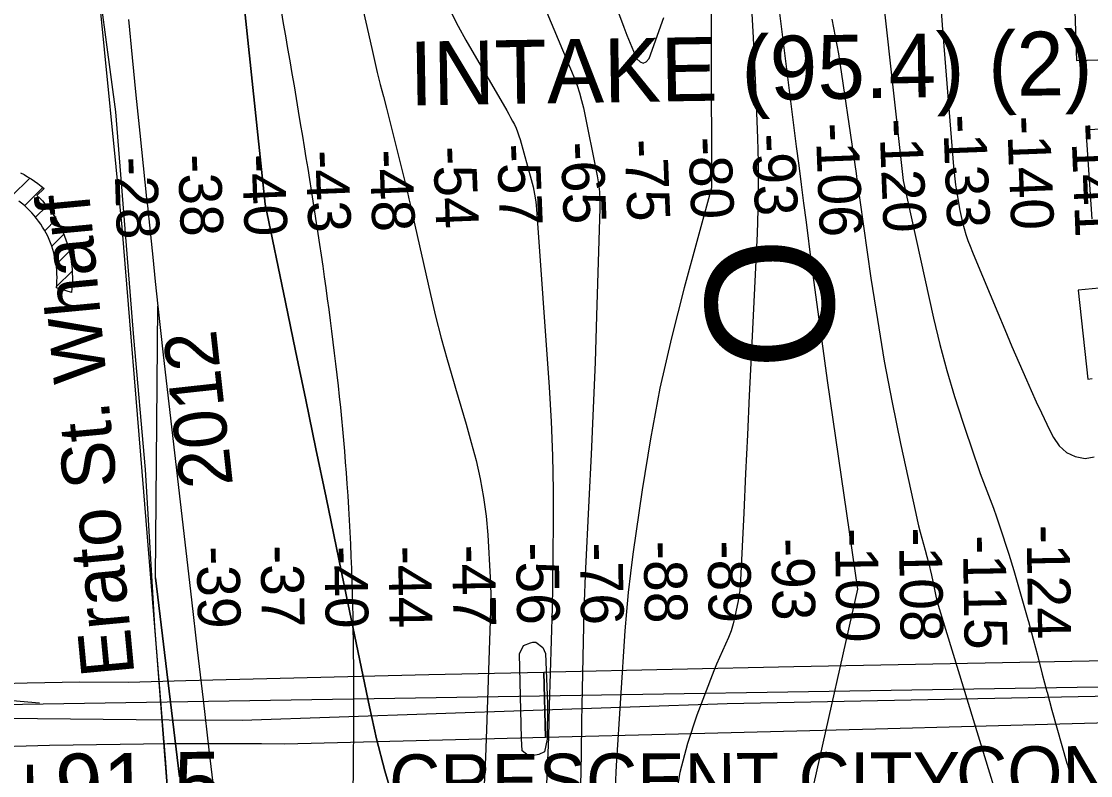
# Model space of a CAD drawing. Extents: x 3677843 to 3715951, y 511991 to 537744.
# Drawn here: x 3683602 to 3685277, y 525377 to 526559 of the extents above; entities that cross this region are included whole.
import ezdxf

# ---------------------------------------------------------------- set-up
doc = ezdxf.new("R2010")
doc.units = 0
for name, color, linetype in [('V-BLDG-IDEN', 7, 'Continuous'), ('V-BLDG-OTLN', 7, 'Continuous'), ('V-BRDG-IDEN', 7, 'Continuous'), ('V-BRDG-OTLN', 7, 'Continuous'), ('V-CHAN-DOCK', 7, 'Continuous'), ('V-CHAN-NAID', 7, 'Continuous'), ('V-RIVR-EDGE', 7, 'Continuous'), ('V-RIVR-FERY', 7, 'Continuous'), ('V-RIVR-IDEN', 7, 'Continuous'), ('V-RIVR-RANG', 7, 'Continuous'), ('V-ROAD-CNTR', 7, 'Continuous'), ('V-RRAP-RVMT', 7, 'Continuous'), ('V-SURV-IDEN', 7, 'Continuous'), ('V-TOPO-DPTH', 7, 'Continuous'), ('V-TOPO-MAJR', 7, 'Continuous'), ('V-TOPO-MINR', 7, 'Continuous')]:
    doc.layers.add(name, color=color, linetype=linetype)

msp = doc.modelspace()

# ---------------------------------------------------------------- linework, layer by layer
at = {"layer": 'V-BLDG-OTLN'}
for p, q in [((3683587, 526285.5), (3683615.4, 526313.9)), ((3683607.3, 526270.5), (3683635.9, 526299.1)), ((3683624.6, 526252.4), (3683642.2, 526270)), ((3683638.9, 526231.4), (3683656.8, 526249.2)), ((3683649.9, 526207), (3683668.6, 526225.7)), ((3683656.7, 526178.4), (3683677.3, 526199)), ((3683657.4, 526143.7), (3683681.8, 526168.2))]:
    msp.add_line(p, q, dxfattribs=at)
msp.add_lwpolyline([(3683600.9, 526322.3), (3683606.5, 526319.3), (3683612.1, 526316), (3683617.5, 526312.6), (3683622.8, 526309), (3683628.1, 526305.3), (3683633.2, 526301.3), (3683638.1, 526297.3), (3683626.7, 526286.7), (3683631, 526282.5), (3683635.1, 526278.2), (3683639.1, 526273.7), (3683642.9, 526269.1), (3683646.6, 526264.4), (3683650.1, 526259.5), (3683653.4, 526254.6), (3683656.6, 526249.5), (3683659.6, 526244.3), (3683662.4, 526239.1), (3683665.1, 526233.7), (3683667.5, 526228.3), (3683669.8, 526222.7), (3683671.9, 526217.1), (3683673.8, 526211.5), (3683675.5, 526205.7), (3683677, 526200), (3683678.4, 526194.1), (3683679.5, 526188.3), (3683680.4, 526182.3), (3683681.1, 526176.4), (3683681.7, 526170.5), (3683682, 526164.5), (3683682.1, 526158.5), (3683682.1, 526152.5), (3683681.8, 526146.6), (3683681.3, 526140.6), (3683680.7, 526134.7), (3683657.2, 526141.6), (3683657.7, 526147.1), (3683658, 526152.6), (3683658.1, 526158.2), (3683658, 526163.7), (3683657.7, 526169.3), (3683657.2, 526174.8), (3683656.4, 526180.3), (3683655.5, 526185.8), (3683654.4, 526191.2), (3683653.1, 526196.6), (3683651.6, 526201.9), (3683649.8, 526207.2), (3683647.9, 526212.4), (3683645.8, 526217.5), (3683643.5, 526222.6), (3683641, 526227.5), (3683638.4, 526232.4), (3683635.5, 526237.1), (3683632.5, 526241.8), (3683629.3, 526246.3), (3683626, 526250.7), (3683622.5, 526255), (3683618.8, 526259.2), (3683615, 526263.2), (3683611, 526267.1), (3683606.9, 526270.8), (3683602.7, 526274.4), (3683598.3, 526277.8)], dxfattribs=at)
at = {"layer": 'V-BRDG-OTLN'}
for points in [[(3685556.5, 525466.8), (3685248.2, 525458.5), (3684939.9, 525450.3), (3684631.6, 525442.3), (3684423.2, 525437), (3684420.3, 525539.7), (3684431.1, 525540), (3684621.6, 525544.2), (3684812.1, 525548.2), (3685002.6, 525552.1), (3685193.1, 525555.7), (3685383.6, 525559.3)], [(3683532.4, 525520.5), (3683611.5, 525523), (3683693.6, 525524.2), (3683769.5, 525524), (3683859.6, 525526.3), (3684050, 525531.1), (3684240.5, 525535.6), (3684420.3, 525539.7), (3684423.2, 525437), (3684323.3, 525434.5), (3684015, 525426.8), (3683978.1, 525427.1), (3683941.3, 525427.2), (3683904.4, 525427.2), (3683867.5, 525427.1), (3683830.7, 525426.9), (3683793.8, 525426.6), (3683756.9, 525426.2), (3683720.1, 525425.7), (3683683.2, 525425), (3683646.4, 525424.3), (3683609.6, 525423.4), (3683572.8, 525422.4)], [(3685676.7, 525509), (3684707.5, 525489.9), (3683947.9, 525463.5), (3683833.5, 525464.4), (3683576, 525466.6)]]:
    msp.add_lwpolyline(points, dxfattribs=at)
at = {"layer": 'V-CHAN-DOCK'}
msp.add_lwpolyline([(3683649.9, 527197.9), (3683684.5, 526911.1), (3683722.7, 526610.6), (3683759.8, 526236.8), (3683793.8, 525822.1), (3683828, 525397.9), (3683832, 525339.2), (3683836.9, 525015), (3683841.6, 524643.6), (3683789.1, 524147.3), (3683702.1, 523509.7), (3683622.2, 523139.4), (3683616.3, 523117.8), (3683492.8, 522808), (3683400.9, 522837.9), (3683364.7, 522761.2)], dxfattribs=at)
msp.add_lwpolyline([(3684382.5, 525568), (3684388.7, 525581.2), (3684399.9, 525585.7), (3684403.1, 525586.5), (3684408, 525586.6), (3684419, 525578.3), (3684423.1, 525568.6), (3684426.3, 525490.2), (3684426, 525434.7), (3684421.8, 525414.4), (3684412.5, 525410.2), (3684401.7, 525408.2), (3684396.2, 525409.1), (3684386.6, 525416), (3684385.4, 525435.7)], close=True, dxfattribs=at)
at = {"layer": 'V-RIVR-EDGE'}
for points in [[(3683541.3, 528059.7), (3683565.2, 527852.5), (3683594.1, 527630.6), (3683620.6, 527429), (3683642.2, 527254.3), (3683665, 527072.2), (3683712.5, 526695.3), (3683749.8, 526417.6), (3683777.7, 526064)], [(3683777.7, 526064), (3683796.2, 525856.9), (3683810.9, 525611.8), (3683829.9, 525361.7)]]:
    msp.add_lwpolyline(points, dxfattribs=at)
at = {"layer": 'V-RIVR-FERY'}
msp.add_spline([(3683395.6, 529471.3), (3683521.9, 529210.1), (3683605.1, 528969.7), (3683680.8, 528445.2), (3683751.5, 527893.7), (3683927.9, 527005.7), (3684042.4, 526379.7), (3684112.2, 525834.6), (3684119.2, 525226.8), (3684092.5, 524348.2), (3684041.6, 523650.6), (3683951.4, 522948.6), (3683790.8, 522287.1), (3683653.8, 521935.8), (3683329.6, 521213.6), (3682839.7, 520457.3), (3682512.6, 519997.8), (3682286.2, 519636), (3682113.5, 519264), (3682089.8, 519186.3)], degree=3, dxfattribs=at)
at = {"layer": 'V-ROAD-CNTR'}
for points in [[(3683630.4, 525490.9), (3683243.5, 525524.3), (3682880.1, 525540.2), (3682607.7, 525556), (3682495.2, 525556)], [(3682737.4, 525473.1), (3683036.3, 525481.1), (3683311.6, 525484.5), (3686098.3, 525529.5)]]:
    msp.add_lwpolyline(points, dxfattribs=at)
at = {"layer": 'V-RRAP-RVMT'}
for points in [[(3685194.2, 526985.7), (3685190.7, 526985.3), (3685205.3, 526846.1), (3685231, 526848.8), (3685238.8, 526741.3), (3685257.9, 526742.5), (3685260.2, 526710.1), (3685240.6, 526705.7), (3685256, 526638.5), (3685249.9, 526638.4), (3685254.8, 526498.2), (3685288, 526499.4)], [(3685311.2, 526392.1), (3685269.2, 526389.1), (3685279, 526249.5)], [(3685301.2, 526142.6), (3685257.2, 526138), (3685272.8, 525998.9), (3685279.6, 525999.6)]]:
    msp.add_lwpolyline(points, dxfattribs=at)
at = {"layer": 'V-TOPO-DPTH'}
for points in [[(3684186.3, 525335.3), (3684171.5, 525384.8), (3684158.7, 525434.8), (3684147.3, 525485.2), (3684111.7, 525658.3), (3684079.6, 525813.1), (3684063.6, 525889.7), (3684047.7, 525966.4), (3684031.8, 526043), (3684015.8, 526119.6), (3683983.9, 526272.9), (3683863.6, 527415.4), (3683862.5, 527425.6), (3683861.3, 527435.8), (3683860, 527446), (3683858.7, 527456.2), (3683840.9, 527586), (3683830.6, 527661.1), (3683820.3, 527736.2), (3683809.9, 527811.3), (3683799.5, 527886.3)], [(3684186.3, 525335.3), (3684171.5, 525384.8), (3684158.7, 525434.8), (3684147.3, 525485.2), (3684111.7, 525658.3), (3684079.6, 525813.1), (3684063.6, 525889.7), (3684047.7, 525966.4), (3684031.8, 526043), (3684015.8, 526119.6), (3683983.9, 526272.9), (3683863.6, 527415.4), (3683862.5, 527425.6), (3683861.3, 527435.8), (3683860, 527446), (3683858.7, 527456.2), (3683840.9, 527586), (3683830.6, 527661.1), (3683820.3, 527736.2), (3683809.9, 527811.3), (3683799.5, 527886.3)], [(3683770, 526562.2), (3683775.7, 526503), (3683781.6, 526443.7), (3683787.7, 526384.5), (3683798.4, 526282.1), (3683799.2, 526274.1), (3683800.1, 526266.1), (3683800.9, 526258.1), (3683801.7, 526250.1), (3683808, 526189.7), (3683812, 526151.5), (3683816.1, 526113.3), (3683820.3, 526075.1), (3683824.6, 526037), (3683868.7, 525652.9), (3683877.7, 525574.5), (3683886.8, 525496.1), (3683896.1, 525417.8), (3683905.5, 525339.4)], [(3683849.7, 525375.4), (3683812.3, 525687.1), (3683816.1, 526113.3)], [(3683816.1, 526113.3), (3683820.3, 526075.1), (3683824.6, 526037), (3683868.7, 525652.9), (3683877.7, 525574.5), (3683886.8, 525496.1), (3683896.1, 525417.8), (3683905.5, 525339.4)]]:
    msp.add_lwpolyline(points, dxfattribs=at)
at = {"layer": 'V-TOPO-MAJR'}
for points in [[(3684601.5, 528093.7), (3684677.6, 527539.5), (3684680.5, 527517.2), (3684683.4, 527495), (3684686.1, 527472.7), (3684688.7, 527450.4), (3684740.9, 526984.5), (3684753.9, 526871), (3684767.1, 526757.5), (3684780.9, 526644.1), (3684794.9, 526530.7), (3684816, 526363.4), (3684819.7, 526333.7), (3684823.5, 526304), (3684827.3, 526274.3), (3684831.2, 526244.6), (3684839.4, 526181), (3684847.6, 526119.6), (3684855.9, 526058.2), (3684864.4, 525996.8), (3684873.2, 525935.5), (3684911.6, 525669.8), (3684843.2, 525365.3)], [(3684109.6, 526700.8), (3684150.9, 526516.8), (3684155.2, 526498.1), (3684159.7, 526479.3), (3684164.4, 526460.6), (3684169.2, 526441.9), (3684174.1, 526423.3), (3684179, 526404.6), (3684183.7, 526385.9), (3684188.3, 526367.2), (3684203.3, 526306.2), (3684206.3, 526293.7), (3684209.3, 526281.2), (3684212.2, 526268.7), (3684215, 526256.2), (3684242.8, 526131.6), (3684250.9, 526097.4), (3684259.5, 526063.2), (3684269, 526029.3), (3684278.9, 525995.6), (3684282.3, 525984.8), (3684290.8, 525956.5), (3684299, 525928.1), (3684306.9, 525899.6), (3684314.4, 525871), (3684321, 525842.3), (3684326.3, 525813.3), (3684330, 525784.1), (3684332.6, 525754.7), (3684336.4, 525687.7), (3684336.9, 525674.6), (3684337.3, 525661.5), (3684337.2, 525648.4), (3684337, 525635.4), (3684330.6, 525449.6), (3684329, 525406.3), (3684327.2, 525363.1)]]:
    msp.add_lwpolyline(points, dxfattribs=at)
at = {"layer": 'V-TOPO-MINR'}
for points in [[(3683799.5, 527886.3), (3683809.9, 527811.3), (3683820.3, 527736.2), (3683830.6, 527661.1), (3683840.9, 527586), (3683858.7, 527456.2), (3683860, 527446), (3683861.3, 527435.8), (3683862.5, 527425.6), (3683863.6, 527415.4), (3683983.9, 526272.9), (3684015.8, 526119.6), (3684031.8, 526043), (3684047.7, 525966.4), (3684063.6, 525889.7), (3684079.6, 525813.1), (3684111.7, 525658.3), (3684147.3, 525485.2), (3684158.7, 525434.8), (3684171.5, 525384.8), (3684186.3, 525335.3)], [(3684860.4, 527419.9), (3684983.2, 526309.9), (3685031.1, 526094.3), (3685041, 526053.1), (3685051.7, 526012.2), (3685063.7, 525971.6), (3685076.6, 525931.2), (3685094.4, 525878.5), (3685099.1, 525864.7), (3685104.1, 525851), (3685109.2, 525837.4), (3685114.5, 525823.8), (3685119.8, 525810.2), (3685124.9, 525796.5), (3685129.7, 525782.7), (3685134.3, 525768.9), (3685148.6, 525724.2), (3685156.5, 525698.8), (3685164.2, 525673.2), (3685171.5, 525647.6), (3685178.6, 525621.9), (3685179.4, 525618.7), (3685186.7, 525591.3), (3685194, 525563.9), (3685201.2, 525536.6), (3685208.5, 525509.2), (3685208.8, 525508), (3685216.3, 525480.1), (3685223.9, 525452.2), (3685231.8, 525424.4), (3685239.9, 525396.6), (3685240.5, 525394.5), (3685248.2, 525365.6)], [(3684681.8, 526965.8), (3684683.4, 526298.8), (3684640.3, 526141.8), (3684620.3, 526063.4), (3684602.3, 525984.5), (3684587.4, 525905), (3684574.4, 525825.1), (3684560, 525724.2), (3684556.1, 525694.4), (3684552.6, 525664.5), (3684549.9, 525634.5), (3684547.6, 525604.5), (3684534, 525393), (3684532.1, 525359.9)], [(3684489.8, 526700.9), (3684546, 526550.6), (3684550.8, 526538), (3684555.7, 526525.4), (3684560.8, 526512.9), (3684566.1, 526500.5), (3684571.2, 526496), (3684576.1, 526494.1), (3684581, 526496.3), (3684585.7, 526501.2), (3684608.4, 526565.3)], [(3685036.4, 526663.3), (3685045.2, 526546.5), (3685062.2, 526332.2), (3685063.1, 526322.5), (3685064.1, 526312.9), (3685065.4, 526303.3), (3685066.9, 526293.7), (3685072.1, 526263.1), (3685074, 526253.6), (3685076.1, 526244.1), (3685078.7, 526234.7), (3685081.6, 526225.4), (3685084.8, 526216.2), (3685088.2, 526207), (3685091.7, 526197.9), (3685095.4, 526188.8), (3685131.5, 526102.5), (3685142.5, 526076.3), (3685153.7, 526050), (3685165, 526023.9), (3685176.5, 525997.8), (3685183.9, 525981.1), (3685191.8, 525963.4), (3685199.9, 525945.8), (3685208.2, 525928.4), (3685216.7, 525910.9), (3685218.6, 525907.2), (3685227.9, 525894.2), (3685239, 525883.9), (3685252.8, 525877.7), (3685268.4, 525874.1), (3685282.3, 525876.8)], [(3684393.9, 526648.8), (3684449.6, 526515.1), (3684454.3, 526503.8), (3684459, 526492.6), (3684463.7, 526481.4), (3684468.4, 526470.1), (3684472.7, 526458.8), (3684476.6, 526447.3), (3684479.8, 526435.6), (3684482.5, 526423.8), (3684503.9, 526317.2), (3684506, 526304.7), (3684507.5, 526292.2), (3684508.1, 526279.6), (3684508.2, 526266.9), (3684503.1, 526097.7), (3684500.7, 526025.3), (3684497.9, 525953), (3684494.7, 525880.6), (3684491.2, 525808.3), (3684485.2, 525691.5), (3684484.5, 525677.6), (3684484, 525663.6), (3684483.5, 525649.7), (3684483.2, 525635.7), (3684481.7, 525562.8), (3684480.7, 525512.3), (3684479.7, 525461.9), (3684478.9, 525411.5), (3684478.1, 525361)], [(3684744, 526610.7), (3684748.4, 526533.5), (3684752, 526456.2), (3684755.1, 526376.2), (3684756.1, 526338.9), (3684756.4, 526301.5), (3684755.8, 526264.2), (3684754.5, 526226.9), (3684745.2, 526034), (3684742.2, 525972.9), (3684739.3, 525911.7), (3684736.5, 525850.6), (3684733.7, 525789.4), (3684728.8, 525683.6), (3684728.2, 525675.4), (3684727.4, 525667.2), (3684726.2, 525659.1), (3684724.7, 525651.1), (3684719.7, 525626.5), (3684716.9, 525615.4), (3684713.7, 525604.5), (3684709.6, 525593.9), (3684705.1, 525583.5), (3684700.2, 525573.1), (3684695.6, 525562.7), (3684691.2, 525552.1), (3684686.9, 525541.5), (3684660.4, 525471.9), (3684645.7, 525427.5), (3684633.7, 525382.4), (3684625.7, 525336.4)], [(3684274.8, 526574.5), (3684286.2, 526552.1), (3684298.4, 526530), (3684362.5, 526419.7), (3684365.6, 526414.2), (3684368.6, 526408.7), (3684371.5, 526403.2), (3684374.4, 526397.6), (3684377, 526391.9), (3684379.4, 526386.2), (3684381.5, 526380.3), (3684383.3, 526374.3), (3684400.9, 526311.4), (3684403.8, 526299.9), (3684406.1, 526288.4), (3684407.8, 526276.7), (3684409, 526264.9), (3684428.7, 525986.1), (3684431.9, 525932.3), (3684434.2, 525878.5), (3684435.1, 525824.6), (3684435.2, 525770.7), (3684434.3, 525685.3), (3684434.2, 525674.1), (3684434, 525662.9), (3684433.7, 525651.7), (3684433.5, 525640.5), (3684429.1, 525486.5), (3684427.6, 525437.4), (3684425.9, 525388.3), (3684423.8, 525339.3)], [(3683770, 526562.2), (3683775.7, 526503), (3683781.6, 526443.7), (3683787.7, 526384.5), (3683798.4, 526282.1), (3683799.2, 526274.1), (3683800.1, 526266.1), (3683800.9, 526258.1), (3683801.7, 526250.1), (3683808, 526189.7), (3683812, 526151.5), (3683816.1, 526113.3), (3683820.3, 526075.1), (3683824.6, 526037), (3683868.7, 525652.9), (3683877.7, 525574.5), (3683886.8, 525496.1), (3683896.1, 525417.8), (3683905.5, 525339.4)], [(3684871.4, 526562.8), (3684877, 526535.8), (3684881.8, 526508.6), (3684907.4, 526335.2), (3684909.5, 526321.2), (3684911.5, 526307.2), (3684913.6, 526293.2), (3684915.6, 526279.2), (3684932.9, 526157.2), (3684942.9, 526092), (3684953.8, 526026.9), (3684966.2, 525962.2), (3684979.4, 525897.6), (3685003.1, 525787.9), (3685005.3, 525778.2), (3685007.6, 525768.7), (3685010.1, 525759.1), (3685012.8, 525749.6), (3685015.4, 525740.1), (3685018, 525730.6), (3685020.4, 525721), (3685022.8, 525711.5), (3685027.5, 525691.7), (3685029.8, 525681.6), (3685032.1, 525671.5), (3685034.2, 525661.4), (3685036.3, 525651.2), (3685134.2, 525330.5)], [(3683812.3, 525687.1), (3683849.7, 525375.4)]]:
    msp.add_lwpolyline(points, dxfattribs=at)

# ---------------------------------------------------------------- texts
at = {"layer": 'V-BLDG-IDEN'}
msp.add_text('Erato St. Wharf', height=83, rotation=95.3837, dxfattribs=at).set_placement((3683779.5, 525536.3))
at = {"layer": 'V-BRDG-IDEN'}
for s, p in [('CONNECTION', (3685066.4, 525339.7)), ('CRESCENT CITY', (3684178.5, 525327.4))]:
    msp.add_text(s, height=83, rotation=0.2523, dxfattribs=at).set_placement(p)
at = {"layer": 'V-CHAN-NAID'}
msp.add_text('INTAKE (95.4) (2)', height=100, rotation=0.907, dxfattribs=at).set_placement((3684210.6, 526427.6))
at = {"layer": 'V-RIVR-IDEN'}
for s, height, rotation, p in [('O', 200, 92.9656, (3684879.6, 526018.6)), ('2012', 83, 96.2706, (3683933.8, 525832.8))]:
    msp.add_text(s, height=height, rotation=rotation, dxfattribs=at).set_placement(p)
at = {"layer": 'V-RIVR-RANG'}
for s, rotation, p in [('-133', 272.2598, (3685045.7, 526412.7)), ('-140', 272.2598, (3685145.9, 526410.3)), ('-106', 272.2598, (3684846.1, 526399.5)), ('-120', 272.2598, (3684945.9, 526406.1)), ('-141', 272.2598, (3685246.4, 526399.2)), ('-80', 272.2598, (3684646.8, 526377.6)), ('-93', 272.2598, (3684746.6, 526382.6)), ('-54', 272.2598, (3684247, 526362.8)), ('-57', 272.2598, (3684347, 526366.8)), ('-65', 272.2598, (3684446.9, 526369.9)), ('-75', 272.2598, (3684546.8, 526374.1)), ('-28', 271.9783, (3683747.7, 526346.3)), ('-38', 272.2598, (3683847.2, 526350.4)), ('-40', 272.2598, (3683947.3, 526350.7)), ('-43', 272.2598, (3684047.1, 526356.7)), ('-48', 272.2598, (3684147.2, 526357.8)), ('-100', 270.9674, (3684876.5, 525764.7)), ('-108', 270.9674, (3684976.5, 525765.9)), ('-124', 270.9674, (3685176.5, 525770.1)), ('-56', 270.9674, (3684376.8, 525742.5)), ('-76', 270.9674, (3684476.8, 525742.3)), ('-88', 270.9674, (3684576.8, 525744.8)), ('-89', 270.9674, (3684676.8, 525745.5)), ('-93', 270.9674, (3684776.8, 525749.3)), ('-115', 270.9674, (3685076.7, 525753.6)), ('-39', 270.9674, (3683876.8, 525736.6)), ('-37', 270.9674, (3683976.8, 525738.3)), ('-40', 270.9674, (3684076.9, 525736.8)), ('-44', 270.9674, (3684176.9, 525737.2)), ('-47', 270.9674, (3684276.9, 525738.9))]:
    msp.add_text(s, height=67, rotation=rotation, dxfattribs=at).set_placement(p)
at = {"layer": 'V-SURV-IDEN'}
msp.add_text('   408+91.5  ', height=100, rotation=0.8688, dxfattribs=at).set_placement((3683243.4, 525305))

doc.saveas('drawing.dxf')
